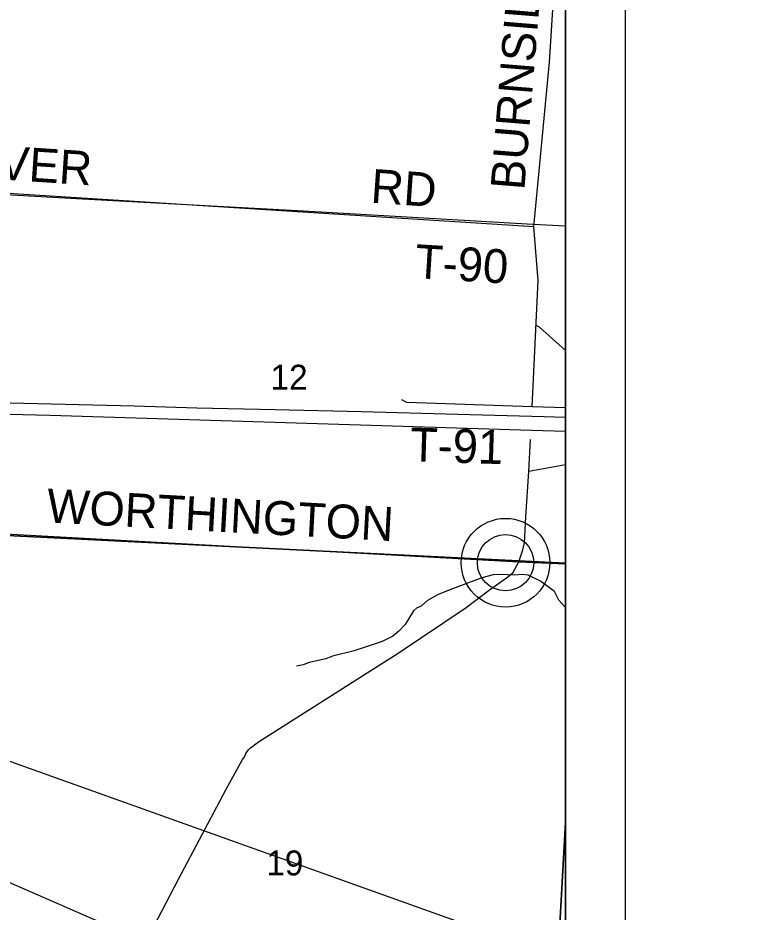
# Model space of a CAD drawing. Extents: x 0 to 91.3, y -0.7 to 22.
# Drawn here: x 7.981 to 9.201, y 16.725 to 18.226 of the extents above; entities that cross this region are included whole.
import ezdxf

# ---------------------------------------------------------------- set-up
doc = ezdxf.new("R2010")
doc.units = 0
for name, color, linetype in [('GM_X_Corporation', 7, 'Continuous'), ('GM_X_County_Road', 7, 'Continuous'), ('GM_X_County_Road_Text', 7, 'Continuous'), ('GM_X_Minor_River', 7, 'Continuous'), ('GM_X_Section_Text', 7, 'Continuous'), ('GM_X_State_Route', 7, 'Continuous'), ('GM_X_Township_Road', 7, 'Continuous'), ('GM_X_Township_Road_Text', 7, 'Continuous'), ('GM_X_Unincorporated', 7, 'Continuous'), ('GM_X_Unincorporated_Location', 7, 'Continuous'), ('SH_Data', 7, 'Continuous'), ('SH_Text', 7, 'Continuous')]:
    doc.layers.add(name, color=color, linetype=linetype)

msp = doc.modelspace()

# ---------------------------------------------------------------- linework, layer by layer
at = {"layer": 'GM_X_Corporation'}
for points in [[(4.8242, 18.6326), (4.7833, 18.1361), (4.7799, 18.0944), (4.7688, 17.9561), (4.7562, 17.8002), (4.7391, 17.5254), (4.7381, 17.5094), (4.7369, 17.4842), (4.7039, 16.921), (4.6966, 16.7952), (4.624, 15.5538), (4.6241, 15.5494), (4.6027, 15.2253), (4.5901, 15.0403), (4.5616, 14.5843), (4.5361, 14.2234), (4.5273, 14.1), (8.9, 14.1), (8.9, 20.9)], [(4.8242, 18.6326), (4.7833, 18.1361), (4.7799, 18.0944), (4.7688, 17.9561), (4.7562, 17.8002), (4.7391, 17.5254), (4.7381, 17.5094), (4.7369, 17.4842), (4.7039, 16.921), (4.6966, 16.7952), (4.624, 15.5538), (4.6241, 15.5494), (5.2553, 15.5081), (5.7371, 15.476), (6.438, 15.425), (7.1732, 15.3725), (7.6407, 15.3389), (8.8181, 15.2648), (8.9, 15.2596), (8.9, 20.4953)]]:
    msp.add_lwpolyline(points, dxfattribs=at)
for points in [[(8.9, 17.3103), (8.9, 17.8759), (8.8451, 17.8791), (8.4604, 17.9014), (8.0797, 17.922), (7.9506, 17.929), (7.9172, 17.3589)], [(8.9, 16.8754), (8.9, 17.3103), (7.9172, 17.3589), (7.8571, 16.3365), (8.8671, 16.2825)], [(8.9, 16.2805), (8.9, 16.8754), (8.8671, 16.2825)]]:
    msp.add_lwpolyline(points, close=True, dxfattribs=at)
at = {"layer": 'GM_X_County_Road'}
msp.add_lwpolyline([(7.0214, 17.4132), (7.1002, 17.4084), (7.2619, 17.3986), (7.4112, 17.39), (8.3263, 17.3397), (8.5262, 17.3288), (8.8216, 17.3124), (8.9, 17.3095)], dxfattribs=at)
at = {"layer": 'GM_X_Minor_River'}
for points in [[(8.9, 17.6675), (8.8561, 17.7063), (8.8508, 17.7094)], [(8.9, 17.2358), (8.8986, 17.2371), (8.8888, 17.2485), (8.8813, 17.2626), (8.8579, 17.2801), (8.8371, 17.2901), (8.8265, 17.2913), (8.8151, 17.2903), (8.7905, 17.2912), (8.7787, 17.2909), (8.7594, 17.286), (8.7104, 17.2674), (8.7031, 17.2648), (8.6849, 17.2573), (8.6685, 17.2475), (8.6575, 17.2385), (8.6499, 17.2351), (8.6449, 17.2302)], [(8.6449, 17.2302), (8.6308, 17.2072), (8.6205, 17.1963), (8.6102, 17.188), (8.5923, 17.179), (8.5452, 17.163), (8.5088, 17.1541), (8.4978, 17.15), (8.4697, 17.1437), (8.4598, 17.1396), (8.4484, 17.1378)]]:
    msp.add_lwpolyline(points, dxfattribs=at)
at = {"layer": 'GM_X_State_Route'}
for points in [[(6.4147, 17.6193), (6.5219, 17.6168), (6.6723, 17.6131), (6.6849, 17.6128), (6.8294, 17.6094), (6.884, 17.6079), (7.0398, 17.6034), (7.2094, 17.5996), (7.3717, 17.5953), (7.4118, 17.5942), (7.5344, 17.5911), (7.7514, 17.5852), (7.9683, 17.5793), (8.1766, 17.5745), (8.2816, 17.5714), (8.4129, 17.5685), (8.5578, 17.5648), (8.7192, 17.5607), (8.864, 17.5567), (8.9, 17.5553)], [(6.4159, 17.5998), (6.677, 17.5931), (6.7472, 17.5914), (6.8769, 17.5882), (7.0303, 17.5836), (7.2161, 17.5792), (7.4145, 17.5739), (7.4356, 17.5734), (8.0357, 17.5587), (8.843, 17.5339), (8.9, 17.5321)]]:
    msp.add_lwpolyline(points, dxfattribs=at)
at = {"layer": 'GM_X_Township_Road'}
msp.add_line((8.9, 17.4757), (8.8384, 17.4644), dxfattribs=at)
for points in [[(8.8439, 17.5728), (8.854, 17.7851), (8.847, 17.875), (8.8729, 18.1514), (8.9, 18.5752)], [(8.847, 17.875), (7.2414, 17.9769), (7.2341, 17.9783)], [(8.9, 17.5709), (8.8439, 17.5728), (8.6337, 17.58), (8.6256, 17.5847)], [(8.8216, 17.3124), (8.8284, 17.333), (8.8312, 17.3443), (8.8334, 17.3882), (8.8384, 17.4644), (8.8412, 17.518)], [(8.1774, 16.6397), (8.2507, 16.78), (8.3301, 16.9302), (8.3582, 16.9806), (8.3601, 16.9836), (8.3623, 16.9878), (8.3638, 16.9912), (8.3657, 16.9943), (8.3683, 16.9973), (8.3714, 17.0004), (8.3755, 17.0035), (8.3804, 17.0069), (8.385, 17.0108), (8.619, 17.1596), (8.7332, 17.2359), (8.7722, 17.2656), (8.8007, 17.2858), (8.8117, 17.2943), (8.8216, 17.3124)]]:
    msp.add_lwpolyline(points, dxfattribs=at)
at = {"layer": 'GM_X_Unincorporated'}
for radius in [0.0744, 0.0472]:
    msp.add_circle((8.7993, 17.3112), radius, dxfattribs=at)
at = {"layer": 'GM_X_Unincorporated_Location'}
msp.add_line((8.7993, 17.3112), (8.7993, 17.3112), dxfattribs=at)
at = {"layer": 'SH_Data'}
for p, q in [((9, 21), (9, 14)), ((8.9, 20.9), (8.9, 14.1))]:
    msp.add_line(p, q, dxfattribs=at)
at = {"layer": 'SH_Text'}
msp.add_lwpolyline([(9.2012, 16.2343), (5.4038, 17.8952), (9.2012, 16.5366)], close=True, dxfattribs=at)

# ---------------------------------------------------------------- texts
at = {"layer": 'GM_X_County_Road_Text'}
msp.add_text('WORTHINGTON', height=0.056818, rotation=356.8862, dxfattribs=at).set_placement((8.0285, 17.379))
at = {"layer": 'GM_X_Section_Text'}
for s, p in [('12', (8.4051, 17.6016)), ('19', (8.398, 16.7863))]:
    msp.add_text(s, height=0.04186, rotation=0, dxfattribs=at).set_placement(p)
at = {"layer": 'GM_X_Township_Road_Text'}
for s, rotation, p in [('BURNSIDE', 85.3612, (8.8308, 17.9355)), ('BEAVER', 356.2203, (7.7962, 17.9648)), ('RD', 356.0531, (8.5721, 17.9156)), ('T-90', 356.4669, (8.6461, 17.7891)), ('T-91', 358.2331, (8.6383, 17.4814))]:
    msp.add_text(s, height=0.05682, rotation=rotation, dxfattribs=at).set_placement(p)

doc.saveas('drawing.dxf')
